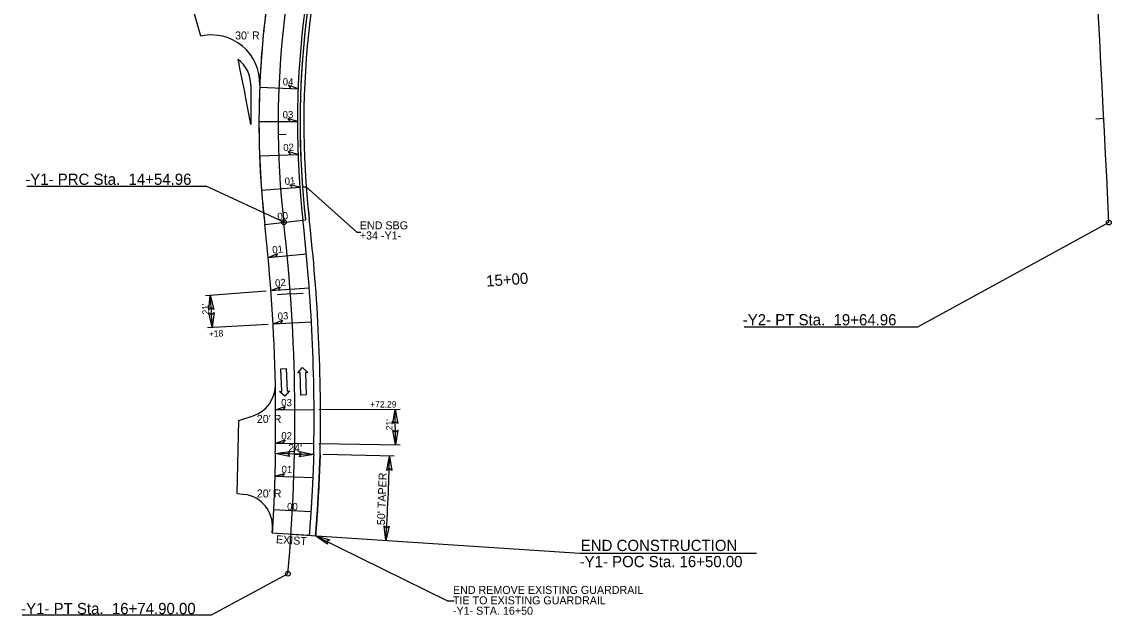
# Model space of a CAD drawing. Extents: x 1616561 to 1622460, y 896726 to 899651.
# Drawn here: x 1619267 to 1619948, y 897404 to 897774 of the extents above; entities that cross this region are included whole.
import ezdxf

# ---------------------------------------------------------------- set-up
doc = ezdxf.new("R2010")
doc.units = 0
for name, color, linetype in [('Old_Level_3', 7, 'Continuous'), ('Prop Conc Curb and Gutter', 7, 'Continuous'), ('Prop Dimension', 7, 'Continuous'), ('Prop DSN Text', 7, 'Continuous'), ('Prop Guardrail', 7, 'Continuous'), ('Prop Horizontal Alignment', 7, 'Continuous'), ('Prop Lane Arrow CELL', 7, 'Continuous'), ('Prop North Arrow NAD83 for Plan Sheets CELL', 7, 'Continuous'), ('Prop Rem of Exist Asph Pvmt', 7, 'Continuous'), ('Prop SBG', 7, 'Continuous'), ('Prop Shade Light', 7, 'Continuous'), ('Prop Superelevation  Arrow CELL', 7, 'Continuous'), ('Prop Superelevation Label', 7, 'Continuous'), ('Prop Terminator CELL', 7, 'Continuous'), ('Sheet Cutting Line CELL', 7, 'Continuous'), ('Sheet North Arrow CELL', 7, 'Continuous'), ('Sheet Sticker Preliminary CELL', 7, 'Continuous')]:
    doc.layers.add(name, color=color, linetype=linetype)

msp = doc.modelspace()

# ---------------------------------------------------------------- linework, layer by layer
at = {"layer": 'Old_Level_3'}
for centre, radius, start, end in [((1619977.61, 897711.39), 562, 160.21645, 186.47628), ((1618353.04, 897526.98), 1073, 358.81708, 1.11607)]:
    msp.add_arc(centre, radius, start, end, dxfattribs=at)
msp.add_spline([(1619425.81, 897504.83), (1619425.8, 897504.16), (1619425.79, 897503.49), (1619425.78, 897502.82), (1619425.77, 897502.15), (1619425.75, 897501.49), (1619425.74, 897500.82), (1619425.73, 897500.15), (1619425.71, 897499.48), (1619425.7, 897498.81), (1619425.69, 897498.15), (1619425.67, 897497.48), (1619425.66, 897496.81), (1619425.64, 897496.14), (1619425.62, 897495.47), (1619425.61, 897494.81), (1619425.59, 897494.14), (1619425.57, 897493.47), (1619425.55, 897492.8), (1619425.54, 897492.13), (1619425.52, 897491.47), (1619425.5, 897490.8), (1619425.48, 897490.13), (1619425.46, 897489.46), (1619425.44, 897488.79), (1619425.42, 897488.13), (1619425.4, 897487.46), (1619425.37, 897486.79), (1619425.35, 897486.12), (1619425.33, 897485.45), (1619425.31, 897484.79), (1619425.28, 897484.12), (1619425.26, 897483.45), (1619425.24, 897482.78), (1619425.21, 897482.11), (1619425.19, 897481.45), (1619425.16, 897480.78), (1619425.13, 897480.11), (1619425.11, 897479.44), (1619425.08, 897478.78), (1619425.05, 897478.11), (1619425.03, 897477.44), (1619425, 897476.77), (1619424.97, 897476.1), (1619424.94, 897475.44), (1619424.91, 897474.77), (1619424.88, 897474.1), (1619424.85, 897473.43), (1619424.82, 897472.77), (1619424.79, 897472.1), (1619424.76, 897471.43), (1619424.73, 897470.76), (1619424.7, 897470.1), (1619424.66, 897469.43), (1619424.63, 897468.76), (1619424.6, 897468.09), (1619424.56, 897467.43), (1619424.53, 897466.76), (1619424.5, 897466.09), (1619424.46, 897465.42), (1619424.43, 897464.76), (1619424.39, 897464.09), (1619424.35, 897463.42), (1619424.32, 897462.75), (1619424.28, 897462.09), (1619424.24, 897461.42), (1619424.2, 897460.75), (1619424.17, 897460.09), (1619424.13, 897459.42), (1619424.09, 897458.75), (1619424.05, 897458.08), (1619424.01, 897457.42), (1619423.97, 897456.75), (1619423.89, 897455.42)], degree=3, dxfattribs=at)
at = {"layer": 'Prop Conc Curb and Gutter'}
msp.add_line((1619379.38, 897765.46), (1619374.68, 897781.57), dxfattribs=at)
for centre, radius, start, end in [((1619977.61, 897711.39), 562, 172.94455, 177.59544), ((1619386.13, 897736.23), 30, 357.59544, 103.01056)]:
    msp.add_arc(centre, radius, start, end, dxfattribs=at)
at = {"layer": 'Prop Dimension'}
for p, q in [((1619449.81, 897504.33), (1619425.81, 897504.83)), ((1619500.14, 897503.29), (1619455.74, 897504.21))]:
    msp.add_line(p, q, dxfattribs=at)
msp.add_arc((1618353.04, 897526.98), 1144.35, 356.17672, 358.81708, dxfattribs=at)
at = {"layer": 'Prop DSN Text'}
for p, q in [((1619476.83, 897643.19), (1619445.11, 897671.42)), ((1619476.83, 897643.19), (1619479.32, 897643.18)), ((1619450.99, 897453.6), (1619533.85, 897412.64)), ((1619537.48, 897412.64), (1619533.85, 897412.64))]:
    msp.add_line(p, q, dxfattribs=at)
at = {"layer": 'Prop Guardrail'}
for centre, radius, start, end in [((1619977.61, 897711.41), 534, 159.92546, 186.47851), ((1618353.04, 897526.98), 1101, 358.81708, 6.47628)]:
    msp.add_arc(centre, radius, start, end, dxfattribs=at)
msp.add_open_spline([(1619450.98, 897453.56), (1619451, 897453.82), (1619451.03, 897454.22), (1619451.07, 897454.64), (1619451.08, 897454.81), (1619451.09, 897454.87), (1619451.09, 897454.91), (1619451.1, 897455), (1619451.11, 897455.2), (1619451.13, 897455.4), (1619451.15, 897455.66), (1619451.16, 897455.8), (1619451.17, 897455.99), (1619451.18, 897456.06), (1619451.19, 897456.19), (1619451.19, 897456.26), (1619451.21, 897456.45), (1619451.3, 897457.64), (1619451.54, 897460.93), (1619452.06, 897468.31), (1619452.71, 897478.86), (1619453.24, 897489.42), (1619453.54, 897496.81), (1619453.68, 897500.5), (1619453.74, 897502.15), (1619453.76, 897502.75), (1619453.76, 897502.85), (1619453.76, 897502.88), (1619453.76, 897502.95), (1619453.76, 897502.98), (1619453.77, 897503.14), (1619453.77, 897503.28), (1619453.78, 897503.54), (1619453.79, 897503.67), (1619453.8, 897503.94), (1619453.8, 897504.07), (1619453.81, 897504.25)], degree=3, dxfattribs=at)
at = {"layer": 'Prop Horizontal Alignment'}
for p, q in [((1619442.78, 897671.25), (1619445.11, 897671.42)), ((1619446.99, 897453.87), (1619450.99, 897453.6))]:
    msp.add_line(p, q, dxfattribs=at)
for centre, radius, start, end in [((1619977.61, 897711.39), 536.33, 160.21645, 184.29289), ((1619977.61, 897711.39), 534, 184.29289, 186.47628), ((1618353.04, 897526.98), 1101, 358.81708, 6.47628)]:
    msp.add_arc(centre, radius, start, end, dxfattribs=at)
msp.add_open_spline([(1619453.81, 897504.25), (1619453.8, 897504.07), (1619453.8, 897503.94), (1619453.79, 897503.67), (1619453.78, 897503.54), (1619453.77, 897503.28), (1619453.77, 897503.14), (1619453.76, 897502.98), (1619453.76, 897502.95), (1619453.76, 897502.88), (1619453.76, 897502.85), (1619453.76, 897502.75), (1619453.74, 897502.15), (1619453.68, 897500.5), (1619453.54, 897496.81), (1619453.24, 897489.42), (1619452.71, 897478.86), (1619452.06, 897468.31), (1619451.54, 897460.93), (1619451.3, 897457.64), (1619451.21, 897456.45), (1619451.19, 897456.26), (1619451.19, 897456.19), (1619451.18, 897456.06), (1619451.17, 897455.99), (1619451.16, 897455.8), (1619451.15, 897455.66), (1619451.13, 897455.4), (1619451.11, 897455.2), (1619451.1, 897455), (1619451.09, 897454.91), (1619451.09, 897454.87), (1619451.08, 897454.81), (1619451.07, 897454.64), (1619451.04, 897454.23), (1619451.01, 897453.85), (1619450.99, 897453.6)], degree=3, dxfattribs=at)
at = {"layer": 'Prop Lane Arrow CELL'}
for p, q in [((1619429.25, 897557.76), (1619432.55, 897557.92)), ((1619429.91, 897543.78), (1619429.25, 897557.76)), ((1619432.55, 897557.92), (1619433.21, 897543.93)), ((1619439.86, 897555.35), (1619442.86, 897558.6)), ((1619442.86, 897558.6), (1619446.16, 897555.55)), ((1619441.36, 897555.4), (1619439.86, 897555.35)), ((1619441.8, 897541.41), (1619441.36, 897555.4)), ((1619446.16, 897555.55), (1619444.66, 897555.5)), ((1619444.66, 897555.5), (1619445.1, 897541.51)), ((1619428.41, 897543.71), (1619429.91, 897543.78)), ((1619431.75, 897540.71), (1619428.41, 897543.71)), ((1619434.7, 897544), (1619431.75, 897540.71)), ((1619433.21, 897543.93), (1619434.7, 897544)), ((1619445.1, 897541.51), (1619441.8, 897541.41))]:
    msp.add_line(p, q, dxfattribs=at)
at = {"layer": 'Prop North Arrow NAD83 for Plan Sheets CELL'}
for points in [[(1619440.03, 897732.7), (1619434.11, 897734.94), (1619435.41, 897732.89)], [(1619439.61, 897712.17), (1619433.61, 897714.18), (1619434.98, 897712.17)], [(1619439.97, 897691.63), (1619433.9, 897693.41), (1619435.35, 897691.46)], [(1619441.12, 897671.12), (1619434.98, 897672.67), (1619436.51, 897670.77)], [(1619421.34, 897627.31), (1619427.13, 897629.86), (1619425.95, 897627.74)], [(1619423.08, 897606.61), (1619428.92, 897609.05), (1619427.69, 897606.96)], [(1619424.42, 897585.89), (1619430.3, 897588.21), (1619429.04, 897586.14)], [(1619426.03, 897532.23), (1619432.02, 897534.26), (1619430.65, 897532.25)], [(1619425.93, 897511.46), (1619431.96, 897513.37), (1619430.55, 897511.39)], [(1619425.49, 897490.7), (1619431.56, 897492.49), (1619430.12, 897490.54)]]:
    msp.add_lwpolyline(points, close=True, dxfattribs=at)
at = {"layer": 'Prop Rem of Exist Asph Pvmt'}
msp.add_line((1619410.45, 897735.15), (1619410.53, 897710.35), dxfattribs=at)
msp.add_arc((1619390.45, 897735.09), 20, 0.18774, 52.80747, dxfattribs=at)
msp.add_spline([(1619410.53, 897710.35), (1619407.26, 897727.9), (1619402.54, 897751.02)], degree=3, dxfattribs=at)
at = {"layer": 'Prop SBG'}
msp.add_arc((1619977.61, 897711.39), 536.33, 160.19269, 184.29289, dxfattribs=at)
at = {"layer": 'Prop Shade Light'}
for p, q in [((1619445.11, 897671.42), (1619442.78, 897671.25)), ((1619443.04, 897650.71), (1619444.7, 897650.9)), ((1619446.99, 897453.87), (1619450.99, 897453.6))]:
    msp.add_line(p, q, dxfattribs=at)
msp.add_lwpolyline([(1619453.81, 897504.2), (1619453.81, 897504.25)], dxfattribs=at)
for centre, radius, start, end in [((1619977.61, 897711.39), 538, 160.21645, 186.47628), ((1619977.61, 897711.39), 536.33, 160.21645, 186.47628), ((1619977.61, 897711.39), 536.33, 184.29289, 186.47628), ((1619977.61, 897711.39), 534, 184.29289, 186.47628), ((1618353.04, 897526.98), 1097, 358.81708, 6.47628), ((1618353.04, 897526.98), 1101, 358.81708, 6.47628)]:
    msp.add_arc(centre, radius, start, end, dxfattribs=at)
for points in [[(1619449.81, 897504.33), (1619449.79, 897503.65), (1619449.76, 897502.97), (1619449.74, 897502.28), (1619449.71, 897501.6), (1619449.69, 897500.92), (1619449.67, 897500.23), (1619449.64, 897499.55), (1619449.62, 897498.87), (1619449.59, 897498.19), (1619449.56, 897497.5), (1619449.54, 897496.82), (1619449.51, 897496.14), (1619449.48, 897495.46), (1619449.45, 897494.77), (1619449.43, 897494.09), (1619449.4, 897493.41), (1619449.37, 897492.73), (1619449.34, 897492.04), (1619449.31, 897491.36), (1619449.28, 897490.68), (1619449.25, 897490), (1619449.21, 897489.31), (1619449.18, 897488.63), (1619449.15, 897487.95), (1619449.13, 897487.5)], [(1619449.13, 897487.5), (1619449.12, 897487.27), (1619449.08, 897486.58), (1619449.05, 897485.9), (1619449.02, 897485.22), (1619448.98, 897484.54), (1619448.95, 897483.86), (1619448.91, 897483.17), (1619448.88, 897482.49), (1619448.84, 897481.81), (1619448.8, 897481.13), (1619448.77, 897480.45), (1619448.73, 897479.76), (1619448.69, 897479.08), (1619448.65, 897478.4), (1619448.61, 897477.72), (1619448.58, 897477.04), (1619448.54, 897476.35), (1619448.5, 897475.67), (1619448.46, 897474.99), (1619448.42, 897474.31), (1619448.37, 897473.63), (1619448.33, 897472.95), (1619448.29, 897472.26), (1619448.25, 897471.58), (1619448.21, 897470.9), (1619448.19, 897470.68)], [(1619448.19, 897470.68), (1619448.16, 897470.22), (1619448.12, 897469.54), (1619448.07, 897468.86), (1619448.03, 897468.17), (1619447.98, 897467.49), (1619447.94, 897466.81), (1619447.89, 897466.13), (1619447.85, 897465.45), (1619447.8, 897464.77), (1619447.75, 897464.09), (1619447.71, 897463.4), (1619447.66, 897462.72), (1619447.61, 897462.04), (1619447.56, 897461.36), (1619447.51, 897460.68), (1619447.46, 897460), (1619447.41, 897459.32), (1619447.36, 897458.64), (1619447.31, 897457.96), (1619447.26, 897457.28), (1619447.21, 897456.59), (1619447.15, 897455.91), (1619447.1, 897455.23), (1619446.99, 897453.87)]]:
    msp.add_spline(points, degree=3, dxfattribs=at)
for points, degree in [([(1619453.7, 897501.03), (1619453.72, 897501.56), (1619453.74, 897502.15), (1619453.76, 897502.75), (1619453.76, 897502.84), (1619453.76, 897502.87), (1619453.76, 897502.9)], 3), ([(1619453.76, 897502.91), (1619453.76, 897502.95), (1619453.76, 897502.98), (1619453.77, 897503.14), (1619453.77, 897503.28), (1619453.78, 897503.41)], 3), ([(1619453.76, 897502.9), (1619453.76, 897502.91), (1619453.76, 897502.91), (1619453.76, 897502.91)], 2), ([(1619453.78, 897503.46), (1619453.78, 897503.57), (1619453.79, 897503.69), (1619453.79, 897503.81), (1619453.79, 897503.82), (1619453.79, 897503.83)], 3), ([(1619453.78, 897503.41), (1619453.78, 897503.42), (1619453.78, 897503.44), (1619453.78, 897503.46)], 2), ([(1619453.79, 897503.83), (1619453.8, 897503.96), (1619453.8, 897504.08), (1619453.81, 897504.2)], 2), ([(1619453.13, 897487.46), (1619453.2, 897488.82), (1619453.36, 897492.28), (1619453.5, 897495.75), (1619453.58, 897497.86)], 3), ([(1619453.58, 897497.86), (1619453.62, 897498.92), (1619453.66, 897499.98), (1619453.7, 897501.03)], 2), ([(1619451.91, 897466.21), (1619452.19, 897470.42), (1619452.63, 897477.51), (1619452.99, 897484.59), (1619453.13, 897487.46)], 3), ([(1619451.19, 897456.28), (1619451.19, 897456.29), (1619451.2, 897456.31), (1619451.21, 897456.45), (1619451.3, 897457.64), (1619451.54, 897460.93), (1619451.77, 897464.1), (1619451.91, 897466.21), (1619451.91, 897466.21)], 3), ([(1619451.03, 897454.16), (1619451.03, 897454.22), (1619451.05, 897454.4), (1619451.06, 897454.59), (1619451.07, 897454.7)], 3), ([(1619451.07, 897454.73), (1619451.07, 897454.73), (1619451.08, 897454.77), (1619451.08, 897454.81), (1619451.08, 897454.84)], 3), ([(1619451.07, 897454.7), (1619451.07, 897454.71), (1619451.07, 897454.72), (1619451.07, 897454.73)], 2), ([(1619451.08, 897454.84), (1619451.09, 897454.87), (1619451.09, 897454.91), (1619451.09, 897454.94)], 2), ([(1619451.09, 897454.94), (1619451.09, 897454.94), (1619451.09, 897454.94), (1619451.09, 897454.98), (1619451.1, 897455.02), (1619451.1, 897455.07)], 3), ([(1619451.1, 897455.07), (1619451.1, 897455.09), (1619451.11, 897455.24), (1619451.13, 897455.4), (1619451.15, 897455.66), (1619451.16, 897455.79), (1619451.17, 897455.92)], 3), ([(1619451.17, 897455.92), (1619451.17, 897455.93), (1619451.17, 897455.93), (1619451.17, 897455.99), (1619451.18, 897456.06), (1619451.18, 897456.13), (1619451.18, 897456.14), (1619451.18, 897456.15)], 3), ([(1619451.18, 897456.15), (1619451.19, 897456.2), (1619451.19, 897456.24), (1619451.19, 897456.28)], 2), ([(1619450.99, 897453.6), (1619451, 897453.79), (1619451.02, 897453.98), (1619451.03, 897454.16)], 2)]:
    msp.add_open_spline(points, degree=degree, dxfattribs=at)
at = {"layer": 'Prop Superelevation  Arrow CELL'}
for p, q in [((1619943.27, 897714), (1619938.28, 897713.75)), ((1619427.66, 897704.18), (1619432.65, 897704.25)), ((1619437.81, 897504.58), (1619442.81, 897504.48))]:
    msp.add_line(p, q, dxfattribs=at)
at = {"layer": 'Prop Superelevation Label'}
for q in [(1619427.29, 897603.94), (1619443.25, 897605.08)]:
    msp.add_line((1619435.27, 897604.51), q, dxfattribs=at)
at = {"layer": 'Prop Terminator CELL'}
for p, q in [((1619379.38, 897765.46), (1619374.68, 897781.57)), ((1619401.99, 897480.04), (1619403.04, 897525.61)), ((1619403.04, 897525.61), (1619411.9, 897528.43)), ((1619401.99, 897480.04), (1619407.18, 897479.23)), ((1619423.89, 897455.42), (1619424.06, 897458.29)), ((1619423.89, 897455.42), (1619446.99, 897453.87))]:
    msp.add_line(p, q, dxfattribs=at)
for points in [[(1619384.31, 897594.7), (1619385.19, 897603.79), (1619387.45, 897594.89), (1619385.77, 897595.91)], [(1619387.53, 897592.87), (1619386.48, 897583.8), (1619384.39, 897592.75), (1619386.05, 897591.69)], [(1619499.24, 897523.59), (1619500.76, 897532.59), (1619502.39, 897523.55), (1619500.78, 897524.69)], [(1619502.35, 897519.38), (1619500.82, 897510.38), (1619499.2, 897519.42), (1619500.8, 897518.28)], [(1619434.78, 897503.09), (1619425.81, 897504.83), (1619434.89, 897506.24), (1619433.71, 897504.66)], [(1619440.84, 897506.07), (1619449.81, 897504.33), (1619440.73, 897502.92), (1619441.91, 897504.49)], [(1619495.41, 897494.39), (1619497.14, 897503.35), (1619498.56, 897494.27), (1619496.98, 897495.46)], [(1619496.99, 897459.55), (1619494.84, 897450.67), (1619493.85, 897459.81), (1619495.37, 897458.56)], [(1619458.37, 897448.23), (1619450.99, 897453.6), (1619459.81, 897451.03), (1619458.07, 897450.1)]]:
    msp.add_lwpolyline(points, close=True, dxfattribs=at)
for centre, radius, start, end in [((1619977.61, 897711.39), 538, 160.21645, 186.47628), ((1619386.13, 897736.23), 30, 357.59544, 103.01056), ((1619977.61, 897711.39), 562, 177.59544, 186.47628), ((1618353.04, 897526.98), 1073, 1.11607, 6.47628), ((1618353.04, 897526.98), 1097, 358.81708, 6.47628), ((1619405.84, 897547.49), 20, 287.63437, 1.11607), ((1619404.09, 897459.47), 20, 356.62684, 81.10338)]:
    msp.add_arc(centre, radius, start, end, dxfattribs=at)
msp.add_spline([(1619449.81, 897504.33), (1619449.79, 897503.65), (1619449.76, 897502.97), (1619449.74, 897502.28), (1619449.71, 897501.6), (1619449.69, 897500.92), (1619449.67, 897500.23), (1619449.64, 897499.55), (1619449.62, 897498.87), (1619449.59, 897498.19), (1619449.56, 897497.5), (1619449.54, 897496.82), (1619449.51, 897496.14), (1619449.48, 897495.46), (1619449.45, 897494.77), (1619449.43, 897494.09), (1619449.4, 897493.41), (1619449.37, 897492.73), (1619449.34, 897492.04), (1619449.31, 897491.36), (1619449.28, 897490.68), (1619449.25, 897490), (1619449.21, 897489.31), (1619449.18, 897488.63), (1619449.15, 897487.95), (1619449.12, 897487.27), (1619449.08, 897486.58), (1619449.05, 897485.9), (1619449.02, 897485.22), (1619448.98, 897484.54), (1619448.95, 897483.86), (1619448.91, 897483.17), (1619448.88, 897482.49), (1619448.84, 897481.81), (1619448.8, 897481.13), (1619448.77, 897480.45), (1619448.73, 897479.76), (1619448.69, 897479.08), (1619448.65, 897478.4), (1619448.61, 897477.72), (1619448.58, 897477.04), (1619448.54, 897476.35), (1619448.5, 897475.67), (1619448.46, 897474.99), (1619448.42, 897474.31), (1619448.37, 897473.63), (1619448.33, 897472.95), (1619448.29, 897472.26), (1619448.25, 897471.58), (1619448.21, 897470.9), (1619448.16, 897470.22), (1619448.12, 897469.54), (1619448.07, 897468.86), (1619448.03, 897468.17), (1619447.98, 897467.49), (1619447.94, 897466.81), (1619447.89, 897466.13), (1619447.85, 897465.45), (1619447.8, 897464.77), (1619447.75, 897464.09), (1619447.71, 897463.4), (1619447.66, 897462.72), (1619447.61, 897462.04), (1619447.56, 897461.36), (1619447.51, 897460.68), (1619447.46, 897460), (1619447.41, 897459.32), (1619447.36, 897458.64), (1619447.31, 897457.96), (1619447.26, 897457.28), (1619447.21, 897456.59), (1619447.15, 897455.91), (1619447.1, 897455.23), (1619446.99, 897453.87)], degree=3, dxfattribs=at)
at = {"layer": 'Sheet Cutting Line CELL'}
for centre, radius, start, end in [((1606187.46, 897021.41), 13773.24, 2.612111, 4.508639), ((1619977.61, 897711.39), 550, 160.21645, 186.47628), ((1618353.04, 897526.98), 1085, 354.86207, 6.47628)]:
    msp.add_arc(centre, radius, start, end, dxfattribs=at)
at = {"layer": 'Sheet North Arrow CELL'}
for p, q in [((1619270.71, 897671.74), (1619382.63, 897671.74)), ((1619431.12, 897649.36), (1619382.63, 897671.74)), ((1619946.39, 897649.12), (1619826.82, 897583.87)), ((1619826.82, 897583.87), (1619718.67, 897583.87)), ((1619435.63, 897454.63), (1619615.96, 897442.58)), ((1619615.96, 897442.58), (1619726.33, 897442.58)), ((1619433.68, 897429.81), (1619385.84, 897403.94)), ((1619385.84, 897403.94), (1619267.8, 897403.94))]:
    msp.add_line(p, q, dxfattribs=at)
for centre in [(1619431.12, 897649.36), (1619946.39, 897649.12), (1619433.68, 897429.81)]:
    msp.add_circle(centre, 1.5, dxfattribs=at)
at = {"layer": 'Sheet Sticker Preliminary CELL'}
for p, q in [((1619416.05, 897733.65), (1619440.03, 897732.7)), ((1619415.61, 897712.2), (1619439.61, 897712.17)), ((1619415.99, 897690.75), (1619439.97, 897691.63)), ((1619417.18, 897669.32), (1619441.12, 897671.12)), ((1619419.2, 897647.96), (1619443.05, 897650.67)), ((1619421.34, 897627.31), (1619445.24, 897629.55)), ((1619382.2, 897603.57), (1619420.09, 897606.39)), ((1619423.08, 897606.61), (1619447.02, 897608.39)), ((1619383.48, 897583.64), (1619421.43, 897585.72)), ((1619424.42, 897585.89), (1619448.39, 897587.21)), ((1619426.03, 897532.23), (1619450.03, 897532.35)), ((1619453.03, 897532.36), (1619503.76, 897532.61)), ((1619500.82, 897510.38), (1619500.76, 897532.59)), ((1619425.93, 897511.46), (1619449.93, 897511.11)), ((1619452.93, 897511.07), (1619503.82, 897510.33)), ((1619425.49, 897490.7), (1619449.24, 897489.89)), ((1619424.69, 897469.94), (1619448.06, 897468.7))]:
    msp.add_line(p, q, dxfattribs=at)
msp.add_arc((1618353.04, 897526.98), 1035, 3.14726, 4.25621, dxfattribs=at)

# ---------------------------------------------------------------- texts
at = {"layer": 'Prop Dimension'}
for s, height, rotation, p in [("30' R", 5, 0.00043, (1619400.67, 897763.45)), ('15+00', 7, 4.09779, (1619557.77, 897609.08)), ("20' R", 5, 0.00043, (1619414.26, 897523.99)), ("24'", 5, 358.81708, (1619433.8, 897505.91)), ("50' TAPER", 5, 87.96539, (1619494.28, 897460.09)), ("20' R", 5, 0.00043, (1619414.27, 897477.45)), ('EXIST', 5, 356.17672, (1619426.1, 897448.9))]:
    msp.add_text(s, height=height, rotation=rotation, dxfattribs=at).set_placement(p)
at = {"layer": 'Prop DSN Text'}
for s, p in [('END SBG', (1619478.59, 897644.88)), ('+34 -Y1-', (1619478.59, 897638.54)), ('END REMOVE EXISTING GUARDRAIL', (1619536.77, 897417.23)), ('TIE TO EXISTING GUARDRAIL', (1619536.77, 897410.73)), ('-Y1- STA. 16+50', (1619536.77, 897404.23))]:
    msp.add_text(s, height=5, dxfattribs=at).set_placement(p)
at = {"layer": 'Sheet North Arrow CELL'}
for s, p in [('-Y1- PRC Sta.  14+54.96', (1619269.64, 897672.67)), ('-Y2- PT Sta.  19+64.96', (1619717.77, 897584.92)), ('END CONSTRUCTION', (1619616.6, 897444.01)), ('-Y1- POC Sta. 16+50.00', (1619615.86, 897433.93)), ('-Y1- PT Sta.  16+74.90.00', (1619267.07, 897404.61))]:
    msp.add_text(s, height=7, rotation=360, dxfattribs=at).set_placement(p)
at = {"layer": 'Sheet Sticker Preliminary CELL'}
for s, height, rotation, p in [('04', 4.5, 358.98001, (1619430.4, 897734.84)), ('03', 4.5, 0.85515, (1619430.41, 897714.22)), ('02', 4.5, 2.73028, (1619430.88, 897693.66)), ('01', 4.5, 4.60542, (1619431.83, 897672.58)), ('00', 4.5, 6.47412, (1619427.38, 897650.6)), ('01', 4.5, 5.52359, (1619424.14, 897629.78)), ('02', 4.5, 4.57306, (1619425.84, 897609.07)), ("21'", 4, 92.85378, (1619384.3, 897591.8)), ('03', 4.5, 3.62253, (1619427.42, 897588.34)), ('+18', 4, 2.48837, (1619384.33, 897577.65)), ('03', 4.5, 359.62417, (1619429.49, 897534.49)), ('+72.29', 4, 359.79484, (1619485.02, 897533.66)), ("21'", 4, 90.16024, (1619499, 897519.45)), ('02', 4.5, 359.62417, (1619429.53, 897513.75)), ('01', 4.5, 358.57971, (1619429.63, 897492.8)), ('00', 4.5, 357.53526, (1619433.08, 897469.71))]:
    msp.add_text(s, height=height, rotation=rotation, dxfattribs=at).set_placement(p)

doc.saveas('drawing.dxf')
